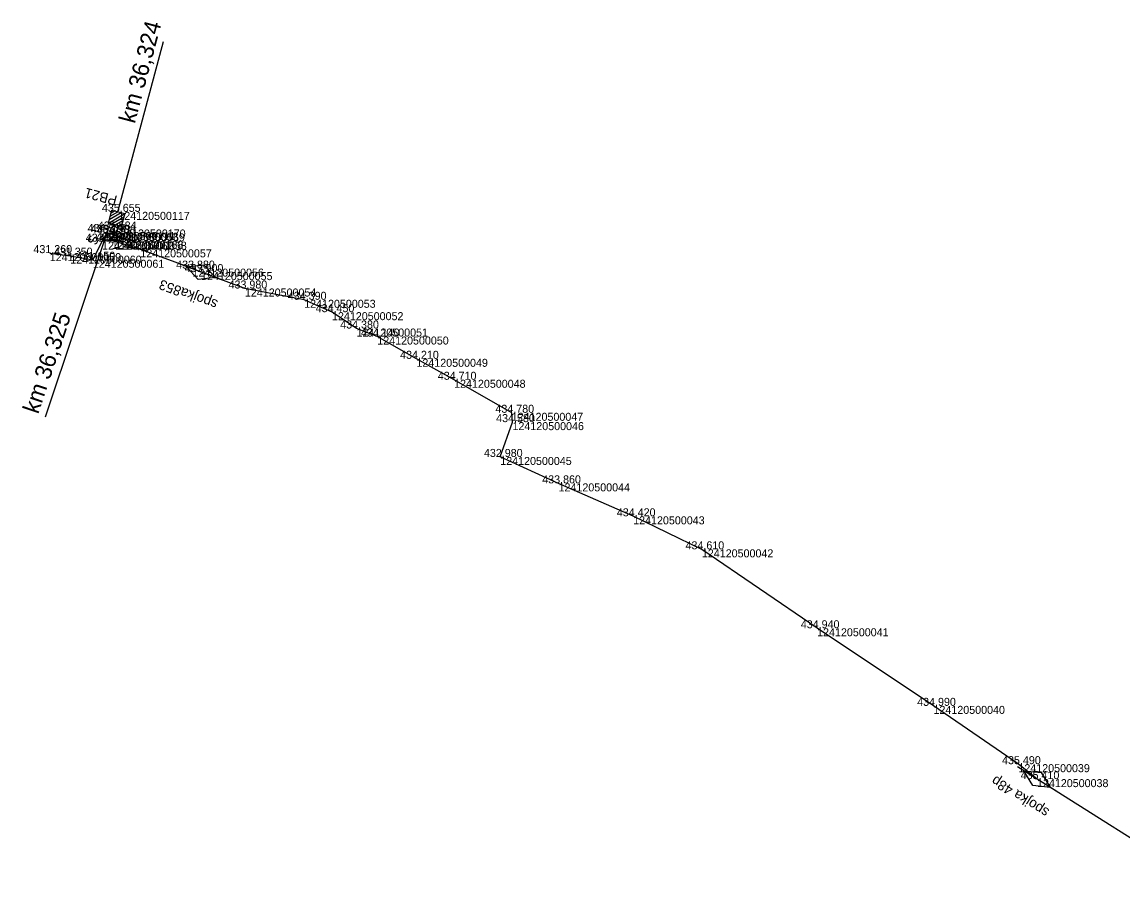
# Model space of a CAD drawing. Extents: x -637342 to -635997, y -1153616 to -1153154.
# Drawn here: x -637342.5 to -637177.6, y -1153282.6 to -1153154.3 of the extents above; entities that cross this region are included whole.
import ezdxf

# ---------------------------------------------------------------- set-up
doc = ezdxf.new("R2010")
doc.units = 0
for name, color, linetype in [('Vrstva 26', 7, 'Continuous'), ('Vrstva 27', 7, 'Continuous'), ('Vrstva 28', 7, 'Continuous'), ('Vrstva 3', 7, 'Continuous'), ('Vrstva 6', 7, 'Continuous'), ('Vrstva 60', 7, 'Continuous'), ('Vrstva 61', 7, 'Continuous')]:
    doc.layers.add(name, color=color, linetype=linetype)

msp = doc.modelspace()

# ---------------------------------------------------------------- linework, layer by layer
at = {"layer": 'Vrstva 26'}
msp.add_lwpolyline([(-637338.33, -1153188.93), (-637335.26, -1153189.31), (-637331.87, -1153189.92), (-637330.49, -1153187.21), (-637329.75, -1153185.87)], dxfattribs=at)
at = {"layer": 'Vrstva 27'}
msp.add_line((-637328.66, -1153185.34), (-637328.68, -1153185.43), dxfattribs=at)
msp.add_circle((-637328.67, -1153185.39), 0.5, dxfattribs=at)
at = {"layer": 'Vrstva 28'}
for p, q in [((-637312.38, -1153192.99), (-637318.92, -1153190.55)), ((-637317.83, -1153190.96), (-637315.24, -1153190.68)), ((-637316.06, -1153192.86), (-637317.83, -1153190.96)), ((-637315.24, -1153190.68), (-637313.47, -1153192.58)), ((-637313.47, -1153192.58), (-637316.06, -1153192.86)), ((-637187.35, -1153269.63), (-637193.25, -1153265.91)), ((-637190.92, -1153268.75), (-637192.27, -1153266.53)), ((-637192.27, -1153266.53), (-637189.68, -1153266.79)), ((-637189.68, -1153266.79), (-637188.33, -1153269.01)), ((-637188.33, -1153269.01), (-637190.92, -1153268.75))]:
    msp.add_line(p, q, dxfattribs=at)
for points in [[(-637328.5, -1153187.21), (-637330.21, -1153185.77), (-637329.75, -1153185.87)], [(-637329.02, -1153187.09), (-637328.79, -1153185.98), (-637328.67, -1153185.39)], [(-637328.5, -1153187.21), (-637329.02, -1153187.09)], [(-637166.83, -1153282.59), (-637190.3, -1153267.77), (-637193.09, -1153265.53), (-637205.82, -1153256.79), (-637223.27, -1153245.16), (-637240.55, -1153233.33), (-637250.85, -1153228.38), (-637262.04, -1153223.44), (-637270.78, -1153219.48), (-637268.95, -1153214.26), (-637269.06, -1153212.86), (-637277.7, -1153207.91), (-637283.35, -1153204.77), (-637289.22, -1153201.43), (-637292.33, -1153200.23), (-637296.01, -1153197.78), (-637300.18, -1153195.92), (-637309.07, -1153194.23), (-637315.65, -1153191.77), (-637316.93, -1153191.25), (-637324.75, -1153188.36), (-637328.5, -1153187.21)]]:
    msp.add_lwpolyline(points, dxfattribs=at)
at = {"layer": 'Vrstva 3'}
for p, q in [((-637328.11, -1153182.73), (-637321.29, -1153157.22)), ((-637329.53, -1153184.42), (-637327.09, -1153183)), ((-637329.4, -1153183.9), (-637327.6, -1153182.86)), ((-637329.26, -1153183.39), (-637328.11, -1153182.73)), ((-637329.12, -1153182.88), (-637328.62, -1153182.59)), ((-637329.02, -1153184.55), (-637327.22, -1153183.51)), ((-637328.51, -1153184.69), (-637327.36, -1153184.02)), ((-637328, -1153184.83), (-637327.5, -1153184.54))]:
    msp.add_line(p, q, dxfattribs=at)
msp.add_lwpolyline([(-637329.02, -1153182.48), (-637327.09, -1153183), (-637327.6, -1153184.93), (-637329.53, -1153184.42)], close=True, dxfattribs=at)
at = {"layer": 'Vrstva 6'}
for p, q in [((-637329.75, -1153185.87), (-637339, -1153213.51)), ((-637329.59, -1153185.4), (-637329.91, -1153186.34)), ((-637327.87, -1153186.5), (-637329.75, -1153185.87))]:
    msp.add_line(p, q, dxfattribs=at)
at = {"layer": 'Vrstva 60'}
for p, q in [((-637328.05, -1153182.74), (-637328.05, -1153182.74)), ((-637330.21, -1153185.77), (-637330.21, -1153185.77)), ((-637329.75, -1153185.87), (-637329.75, -1153185.87)), ((-637328.79, -1153185.98), (-637328.79, -1153185.98)), ((-637328.67, -1153185.39), (-637328.67, -1153185.39)), ((-637330.49, -1153187.21), (-637330.49, -1153187.21)), ((-637329.02, -1153187.09), (-637329.02, -1153187.09)), ((-637328.5, -1153187.21), (-637328.5, -1153187.21)), ((-637324.75, -1153188.36), (-637324.75, -1153188.36)), ((-637338.33, -1153188.93), (-637338.33, -1153188.93)), ((-637335.26, -1153189.31), (-637335.26, -1153189.31)), ((-637331.87, -1153189.92), (-637331.87, -1153189.92)), ((-637316.93, -1153191.25), (-637316.93, -1153191.25)), ((-637315.65, -1153191.77), (-637315.65, -1153191.77)), ((-637309.07, -1153194.23), (-637309.07, -1153194.23)), ((-637300.18, -1153195.92), (-637300.18, -1153195.92)), ((-637296.01, -1153197.78), (-637296.01, -1153197.78)), ((-637292.33, -1153200.23), (-637292.33, -1153200.23)), ((-637289.22, -1153201.43), (-637289.22, -1153201.43)), ((-637283.35, -1153204.77), (-637283.35, -1153204.77)), ((-637277.7, -1153207.91), (-637277.7, -1153207.91)), ((-637269.06, -1153212.86), (-637269.06, -1153212.86)), ((-637268.95, -1153214.26), (-637268.95, -1153214.26)), ((-637270.78, -1153219.48), (-637270.78, -1153219.48)), ((-637262.04, -1153223.44), (-637262.04, -1153223.44)), ((-637250.85, -1153228.38), (-637250.85, -1153228.38)), ((-637240.55, -1153233.33), (-637240.55, -1153233.33)), ((-637223.27, -1153245.16), (-637223.27, -1153245.16)), ((-637205.82, -1153256.79), (-637205.82, -1153256.79)), ((-637193.09, -1153265.53), (-637193.09, -1153265.53)), ((-637190.3, -1153267.77), (-637190.3, -1153267.77))]:
    msp.add_line(p, q, dxfattribs=at)

# ---------------------------------------------------------------- texts
at = {"layer": 'Vrstva 28'}
for s, rotation, p in [('spojka853', 159.5012, (-637313.02, -1153196.05)), ('spojka 48p', 147.7299, (-637188.34, -1153272.38))]:
    msp.add_text(s, height=1.5, rotation=rotation, dxfattribs=at).set_placement(p)
at = {"layer": 'Vrstva 3'}
for s, height, rotation, p in [('km 36,324', 2.5, 75.052, (-637325.59, -1153169.61)), ('PB21', 1.5, 165.052, (-637328.11, -1153180.38))]:
    msp.add_text(s, height=height, rotation=rotation, dxfattribs=at).set_placement(p)
at = {"layer": 'Vrstva 6'}
for s, height, rotation, p in [('S', 1.5, 71.4954, (-637331.33, -1153187.83)), ('  A A A A A ', 1, 341.4954, (-637330.07, -1153186.82)), ('km 36,325', 2.5, 71.4954, (-637340.07, -1153213.15))]:
    msp.add_text(s, height=height, rotation=rotation, dxfattribs=at).set_placement(p)
at = {"layer": 'Vrstva 60'}
for s, p in [('124120500117', (-637328.05, -1153183.94)), ('124120500111', (-637330.21, -1153186.97)), ('124120500063', (-637329.75, -1153187.07)), ('124120500169', (-637328.79, -1153187.18)), ('124120500170', (-637328.67, -1153186.58)), ('124120500062', (-637330.49, -1153188.41)), ('124120500168', (-637329.02, -1153188.29)), ('124120500058', (-637328.5, -1153188.41)), ('124120500057', (-637324.75, -1153189.56)), ('124120500059', (-637338.33, -1153190.13)), ('124120500060', (-637335.26, -1153190.51)), ('124120500061', (-637331.87, -1153191.12)), ('124120500056', (-637316.93, -1153192.45)), ('124120500055', (-637315.65, -1153192.97)), ('124120500054', (-637309.07, -1153195.43)), ('124120500053', (-637300.18, -1153197.12)), ('124120500052', (-637296.01, -1153198.98)), ('124120500051', (-637292.33, -1153201.43)), ('124120500050', (-637289.22, -1153202.63)), ('124120500049', (-637283.35, -1153205.97)), ('124120500048', (-637277.7, -1153209.11)), ('124120500047', (-637269.06, -1153214.06)), ('124120500046', (-637268.95, -1153215.46)), ('124120500045', (-637270.78, -1153220.68)), ('124120500044', (-637262.04, -1153224.64)), ('124120500043', (-637250.85, -1153229.58)), ('124120500042', (-637240.55, -1153234.53)), ('124120500041', (-637223.27, -1153246.36)), ('124120500040', (-637205.82, -1153257.99)), ('124120500039', (-637193.09, -1153266.73)), ('124120500038', (-637190.3, -1153268.97))]:
    msp.add_text(s, height=1.2, dxfattribs=at).set_placement(p)
at = {"layer": 'Vrstva 61'}
for s, p in [('435.655', (-637330.51, -1153182.74)), ('434.510', (-637332.66, -1153185.77)), ('435.190', (-637332.2, -1153185.87)), ('434.238', (-637331.25, -1153185.98)), ('435.584', (-637331.12, -1153185.39)), ('433.550', (-637332.94, -1153187.21)), ('433.571', (-637331.37, -1153187.09)), ('434.190', (-637330.95, -1153187.21)), ('431.260', (-637340.78, -1153188.93)), ('431.350', (-637337.71, -1153189.31)), ('433.870', (-637327.2, -1153188.36)), ('431.150', (-637334.32, -1153189.92)), ('433.880', (-637319.38, -1153191.25)), ('433.900', (-637318.1, -1153191.77)), ('433.980', (-637311.52, -1153194.23)), ('434.390', (-637302.63, -1153195.92)), ('434.450', (-637298.46, -1153197.78)), ('434.380', (-637294.78, -1153200.23)), ('434.140', (-637291.67, -1153201.43)), ('434.210', (-637285.8, -1153204.77)), ('434.710', (-637280.15, -1153207.91)), ('434.780', (-637271.51, -1153212.86)), ('434.580', (-637271.4, -1153214.26)), ('432.980', (-637273.23, -1153219.48)), ('433.860', (-637264.49, -1153223.44)), ('434.420', (-637253.3, -1153228.38)), ('434.610', (-637243, -1153233.33)), ('434.940', (-637225.72, -1153245.16)), ('434.990', (-637208.27, -1153256.79)), ('435.490', (-637195.54, -1153265.53)), ('435.410', (-637192.75, -1153267.77))]:
    msp.add_text(s, height=1.2, dxfattribs=at).set_placement(p)

doc.saveas('drawing.dxf')
